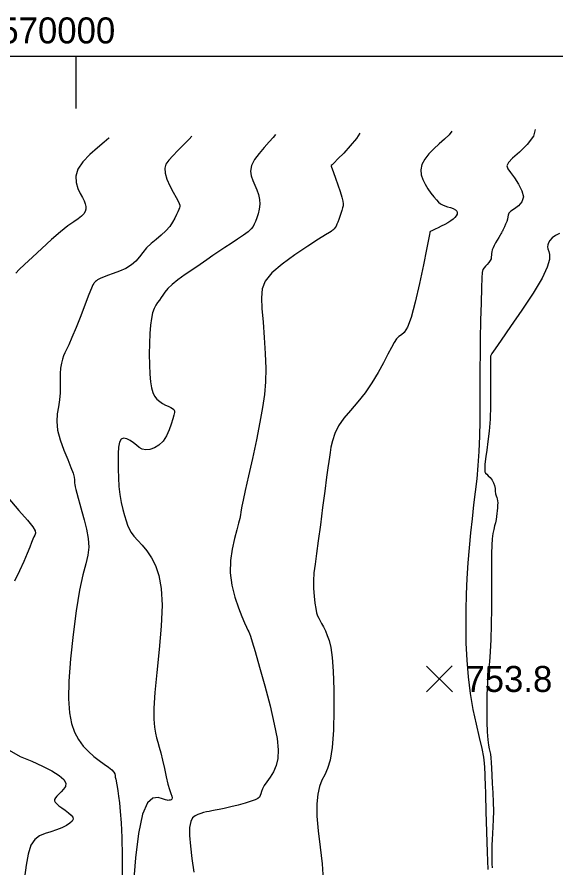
# Model space of a CAD drawing. Extents: x 2566142 to 2571431, y 418755 to 421584.
# Drawn here: x 2569965.9 to 2570277, y 421093.3 to 421584.4 of the extents above; entities that cross this region are included whole.
import ezdxf

# ---------------------------------------------------------------- set-up
doc = ezdxf.new("R2010")
doc.units = 0
for name, color, linetype in [('Contour_ADS_Major', 7, 'Continuous'), ('Contour_ADS_Minor', 7, 'Continuous'), ('Contour_ADS_Spot_Elevation', 7, 'Continuous'), ('Contour_ADS_State_Plane_Border', 7, 'Continuous')]:
    doc.layers.add(name, color=color, linetype=linetype)

# ---------------------------------------------------------------- blocks, each defined once
blk = doc.blocks.new('S750')
at = {"layer": 'Contour_ADS_Spot_Elevation'}
for p, q in [((-0.5, 0.498), (0.5, -0.498)), ((-0.498, -0.5), (0.498, 0.5))]:
    blk.add_line(p, q, dxfattribs=at)

msp = doc.modelspace()

# ---------------------------------------------------------------- linework, layer by layer
at = {"layer": 'Contour_ADS_Major'}
for points in [[(2570163.72, 421517.45), (2570161.83, 421514.35), (2570158.31, 421510.02), (2570154.48, 421505.88), (2570151.16, 421502.51), (2570148.99, 421500.32), (2570147.82, 421499.13), (2570147.34, 421498.61), (2570147.22, 421498.44), (2570147.22, 421498.28), (2570147.37, 421497.81), (2570147.76, 421496.71), (2570148.51, 421494.64), (2570149.67, 421491.45), (2570151.03, 421487.6), (2570152.37, 421483.69), (2570153.43, 421480.35), (2570154.03, 421478.04), (2570154.21, 421476.51), (2570154.09, 421475.37), (2570153.77, 421474.22), (2570153.34, 421472.75), (2570152.84, 421471.04), (2570152.29, 421469.25), (2570151.72, 421467.54), (2570151.16, 421466.04), (2570150.6, 421464.77), (2570150.05, 421463.72), (2570149.53, 421462.87), (2570149.03, 421462.2), (2570148.56, 421461.69), (2570148.13, 421461.29), (2570147.73, 421461), (2570147.27, 421460.69), (2570146.23, 421460.04), (2570143.99, 421458.64), (2570139.93, 421456.09), (2570133.74, 421452.13), (2570126.35, 421447.2), (2570119.02, 421441.85), (2570113, 421436.67), (2570109.22, 421432.02), (2570107.41, 421427.48), (2570106.97, 421422.39), (2570107.32, 421416.12), (2570107.95, 421408.26), (2570108.61, 421399.35), (2570109.16, 421390.15), (2570109.45, 421381.45), (2570109.34, 421373.76), (2570108.77, 421366.55), (2570107.71, 421359.06), (2570106.14, 421350.49), (2570104.07, 421340.41), (2570101.76, 421329.69), (2570099.52, 421319.56), (2570097.68, 421311.22), (2570096.46, 421305.55), (2570095.77, 421302.09), (2570095.39, 421300.04), (2570095.16, 421298.59), (2570094.89, 421297.03), (2570094.47, 421295), (2570093.82, 421292.21), (2570092.83, 421288.4), (2570091.49, 421283.38), (2570090.14, 421277.36), (2570089.18, 421270.65), (2570089.02, 421263.56), (2570089.94, 421256.41), (2570091.64, 421249.57), (2570093.7, 421243.43), (2570095.67, 421238.38), (2570097.22, 421234.69), (2570098.36, 421232.17), (2570099.16, 421230.54), (2570099.72, 421229.48), (2570100.16, 421228.6), (2570100.74, 421227.05), (2570101.73, 421223.88), (2570103.42, 421218.13), (2570105.95, 421209.25), (2570108.97, 421198.33), (2570111.97, 421186.86), (2570114.44, 421176.34), (2570115.99, 421167.93), (2570116.61, 421161.47), (2570116.4, 421156.45), (2570115.45, 421152.38), (2570113.9, 421148.85), (2570112.03, 421145.75), (2570110.14, 421143.08), (2570108.58, 421140.81), (2570107.56, 421138.93), (2570106.97, 421137.39), (2570106.62, 421136.12), (2570106.32, 421135.09), (2570105.85, 421134.22), (2570104.97, 421133.43), (2570103.45, 421132.64), (2570101.02, 421131.75)], [(2570101.02, 421131.75), (2570097.57, 421130.72), (2570093.49, 421129.62), (2570089.3, 421128.57), (2570085.52, 421127.67), (2570082.54, 421127.02), (2570080.25, 421126.56), (2570078.42, 421126.22), (2570076.81, 421125.93), (2570075.21, 421125.62), (2570073.6, 421125.24), (2570071.97, 421124.78), (2570070.34, 421124.2), (2570068.73, 421123.42), (2570067.28, 421122.15), (2570066.16, 421120.03), (2570065.52, 421116.71), (2570065.48, 421111.94), (2570065.96, 421105.88), (2570066.81, 421098.78), (2570067.91, 421090.91)]]:
    msp.add_lwpolyline(points, dxfattribs=at)
at = {"layer": 'Contour_ADS_Minor'}
for points in [[(2570115.17, 421516.52), (2570113.72, 421514.8), (2570111.39, 421512.28), (2570108.56, 421509.17), (2570105.62, 421505.68), (2570103.05, 421502.07), (2570101.29, 421498.61), (2570100.68, 421495.51), (2570101.02, 421492.71), (2570101.95, 421490.06), (2570103.14, 421487.44), (2570104.28, 421484.74), (2570105.22, 421481.97), (2570105.85, 421479.15), (2570106.04, 421476.32), (2570105.74, 421473.53), (2570105.09, 421470.88), (2570104.28, 421468.48), (2570103.51, 421466.44), (2570102.87, 421464.83), (2570102.16, 421463.45), (2570101.07, 421462.09), (2570099.27, 421460.5), (2570096.59, 421458.52), (2570093.23, 421456.23), (2570089.53, 421453.78), (2570085.81, 421451.33), (2570082.33, 421448.99), (2570078.95, 421446.67), (2570075.45, 421444.26), (2570071.62, 421441.65), (2570067.35, 421438.76), (2570062.94, 421435.73), (2570058.82, 421432.75), (2570055.38, 421430.01), (2570052.93, 421427.65), (2570051.27, 421425.65), (2570050.12, 421423.93), (2570049.15, 421422.43), (2570048.13, 421421.05), (2570047.06, 421419.65), (2570046, 421418.05), (2570045.01, 421416.09), (2570044.15, 421413.58), (2570043.44, 421410.43), (2570042.89, 421406.5), (2570042.51, 421401.68), (2570042.3, 421395.96), (2570042.27, 421389.78), (2570042.38, 421383.69), (2570042.63, 421378.24), (2570043, 421373.84), (2570043.54, 421370.41), (2570044.31, 421367.75), (2570045.35, 421365.65), (2570046.7, 421363.93), (2570048.28, 421362.52), (2570049.96, 421361.39), (2570051.64, 421360.47), (2570053.21, 421359.74), (2570054.6, 421359.11), (2570055.72, 421358.53), (2570056.49, 421357.9), (2570056.86, 421357.16), (2570056.85, 421356.12), (2570056.51, 421354.61), (2570055.87, 421352.43), (2570054.96, 421349.49), (2570053.75, 421346.11), (2570052.18, 421342.7), (2570050.21, 421339.65), (2570047.82, 421337.31), (2570045.2, 421335.71), (2570042.59, 421334.83), (2570040.2, 421334.64), (2570038.21, 421335.08), (2570036.49, 421336), (2570034.87, 421337.24), (2570033.16, 421338.64), (2570031.25, 421339.99), (2570029.27, 421341.02), (2570027.44, 421341.39), (2570025.97, 421340.79), (2570025.02, 421338.99), (2570024.5, 421336.13), (2570024.29, 421332.42), (2570024.26, 421328.1), (2570024.3, 421323.38), (2570024.44, 421318.45), (2570024.73, 421313.51), (2570025.24, 421308.73), (2570025.99, 421304.28), (2570026.91, 421300.24), (2570027.9, 421296.66), (2570028.86, 421293.61), (2570029.73, 421291.1), (2570030.66, 421288.95), (2570031.82, 421286.92), (2570033.41, 421284.79), (2570035.55, 421282.36), (2570038.07, 421279.53)], [(2570216.92, 421518.47), (2570215.29, 421516.43), (2570212.69, 421513.96), (2570209.68, 421511.27), (2570206.58, 421508.37), (2570203.7, 421505.34), (2570201.31, 421502.26), (2570199.69, 421499.2), (2570199.05, 421496.23), (2570199.25, 421493.35), (2570200.12, 421490.56), (2570201.45, 421487.86), (2570203.05, 421485.24), (2570204.78, 421482.8), (2570206.48, 421480.64), (2570208.01, 421478.87), (2570209.27, 421477.56), (2570210.39, 421476.62), (2570211.51, 421475.95), (2570212.82, 421475.41), (2570214.4, 421474.91), (2570216.11, 421474.4), (2570217.71, 421473.84), (2570218.99, 421473.19), (2570219.77, 421472.44), (2570220.07, 421471.59), (2570219.94, 421470.67), (2570219.47, 421469.7), (2570218.69, 421468.71), (2570217.63, 421467.7), (2570216.29, 421466.68), (2570214.66, 421465.65), (2570212.8, 421464.62), (2570210.84, 421463.63), (2570208.97, 421462.74), (2570207.38, 421462), (2570206.19, 421461.44), (2570205.38, 421461.05), (2570204.86, 421460.78), (2570204.55, 421460.6), (2570204.36, 421460.47), (2570204.26, 421460.38), (2570204.23, 421460.31), (2570204.23, 421460.24), (2570204.2, 421460.02), (2570204, 421458.88), (2570203.43, 421455.91), (2570202.3, 421450.2), (2570200.5, 421441.29), (2570198.23, 421430.57), (2570195.76, 421419.87), (2570193.36, 421411.03), (2570191.23, 421405.39), (2570189.39, 421402.38), (2570187.78, 421400.94), (2570186.35, 421400), (2570185.02, 421398.65), (2570183.64, 421396.6), (2570182.02, 421393.69), (2570179.99, 421389.79), (2570177.41, 421384.85), (2570174.31, 421379.2), (2570170.76, 421373.27), (2570166.82, 421367.5), (2570162.62, 421362.22), (2570158.44, 421357.37), (2570154.63, 421352.81), (2570151.51, 421348.4), (2570149.34, 421344.04), (2570147.97, 421339.87), (2570147.15, 421336.12), (2570146.65, 421332.97), (2570146.26, 421330.46), (2570145.85, 421327.86), (2570145.32, 421324.27), (2570144.58, 421318.78), (2570143.56, 421310.84), (2570142.35, 421301.3), (2570141.07, 421291.34), (2570139.84, 421282.17), (2570138.78, 421274.69), (2570137.93, 421268.69), (2570137.34, 421263.64), (2570137.05, 421259.03), (2570137.08, 421254.48), (2570137.37, 421250.11), (2570137.82, 421246.18), (2570138.34, 421242.94), (2570138.87, 421240.55), (2570139.43, 421238.81), (2570140.07, 421237.39), (2570140.83, 421235.99), (2570141.76, 421234.35), (2570142.81, 421232.4), (2570143.92, 421230.13), (2570145.04, 421227.54), (2570146.09, 421224.49), (2570147.05, 421220.45), (2570147.85, 421214.78), (2570148.46, 421206.84), (2570148.82, 421196.33)], [(2570265.06, 421519.39), (2570264.04, 421515.66), (2570260.47, 421510.83), (2570256.01, 421506.42), (2570252.01, 421502.84), (2570249.58, 421500.36), (2570248.73, 421498.56), (2570249.2, 421496.86), (2570250.74, 421494.67), (2570253.03, 421491.58), (2570255.47, 421487.89), (2570257.42, 421484.06), (2570258.2, 421480.53), (2570257.38, 421477.69), (2570255.45, 421475.47), (2570253.11, 421473.75), (2570251.07, 421472.38), (2570249.87, 421471.21), (2570249.35, 421470.13), (2570249.17, 421469.03), (2570249, 421467.8), (2570248.59, 421466.35), (2570247.99, 421464.83), (2570247.33, 421463.39), (2570246.75, 421462.2), (2570246.35, 421461.39), (2570246.11, 421460.89), (2570245.97, 421460.6), (2570245.87, 421460.4), (2570245.75, 421460.19), (2570245.57, 421459.87), (2570245.25, 421459.31), (2570244.74, 421458.43), (2570244, 421457.16), (2570243.12, 421455.63), (2570242.21, 421454), (2570241.38, 421452.45), (2570240.73, 421451.11), (2570240.25, 421449.95), (2570239.95, 421448.92), (2570239.79, 421447.93), (2570239.74, 421446.94), (2570239.7, 421445.93), (2570239.53, 421444.89), (2570239.11, 421443.82), (2570238.35, 421442.71), (2570237.38, 421441.61), (2570236.37, 421440.57), (2570235.49, 421439.62), (2570234.87, 421438.68), (2570234.46, 421437.02), (2570234.2, 421433.78), (2570233.99, 421428.11), (2570233.77, 421419.53), (2570233.54, 421409.17), (2570233.34, 421398.56), (2570233.2, 421389.22), (2570233.12, 421382.23), (2570233.1, 421376.88), (2570233.12, 421372.02), (2570233.14, 421366.49), (2570233.14, 421359.43), (2570233.08, 421351.19), (2570232.89, 421342.4), (2570232.54, 421333.7), (2570231.99, 421325.57), (2570231.26, 421317.9), (2570230.42, 421310.4), (2570229.51, 421302.8), (2570228.58, 421294.87), (2570227.68, 421286.61), (2570226.86, 421278.08), (2570226.14, 421269.33), (2570225.58, 421260.41), (2570225.18, 421251.32), (2570224.96, 421242.06), (2570224.93, 421232.6), (2570225.09, 421222.96), (2570225.52, 421213.24), (2570226.3, 421203.56), (2570227.48, 421194.04), (2570229.1, 421184.83), (2570230.94, 421176.23), (2570232.73, 421168.56), (2570234.19, 421162.17), (2570235.13, 421157.27), (2570235.63, 421153.72), (2570235.83, 421151.27), (2570235.87, 421149.68), (2570235.9, 421148.72), (2570235.92, 421148.21), (2570235.93, 421147.99), (2570235.95, 421147.91), (2570235.95, 421147.85), (2570235.96, 421147.76), (2570235.96, 421147.64), (2570235.97, 421147.5), (2570235.98, 421147.34), (2570235.99, 421147.16), (2570236, 421146.98), (2570236, 421146.8)], [(2570019.19, 421514.69), (2570018.92, 421514.45), (2570016.17, 421512.15), (2570012.32, 421508.96), (2570007.98, 421505.08), (2570003.96, 421500.85), (2570001.05, 421496.58), (2569999.84, 421492.54), (2570000.01, 421488.83), (2570001.04, 421485.51), (2570002.4, 421482.63), (2570003.62, 421480.23), (2570004.6, 421478.23), (2570005.29, 421476.51), (2570005.66, 421474.97), (2570005.67, 421473.52), (2570005.27, 421472.12), (2570004.42, 421470.75), (2570003.08, 421469.39), (2570001.19, 421467.96), (2569998.63, 421466.2), (2569995.28, 421463.79), (2569990.99, 421460.41), (2569985.77, 421455.91), (2569980.14, 421450.82), (2569974.77, 421445.81), (2569970.29, 421441.59), (2569967.18, 421438.64), (2569965.12, 421436.63)], [(2570066.77, 421515.6), (2570065.2, 421513.96), (2570062.04, 421510.7), (2570058.79, 421507.33), (2570055.82, 421504.25), (2570053.47, 421501.71), (2570051.88, 421499.46), (2570051.14, 421497.13), (2570051.33, 421494.34), (2570052.45, 421490.87), (2570054.17, 421487.05), (2570056.07, 421483.35), (2570057.77, 421480.24), (2570058.92, 421478.07), (2570059.56, 421476.68), (2570059.81, 421475.76), (2570059.8, 421475.03), (2570059.61, 421474.22), (2570059.26, 421473.22), (2570058.73, 421471.95), (2570057.99, 421470.34), (2570057.01, 421468.34), (2570055.72, 421466.03), (2570054.03, 421463.55), (2570051.86, 421461.02), (2570049.18, 421458.53), (2570046.21, 421456.08), (2570043.26, 421453.61), (2570040.62, 421451.11), (2570038.47, 421448.53), (2570036.56, 421445.98), (2570034.52, 421443.53), (2570031.98, 421441.29), (2570028.72, 421439.34), (2570025.03, 421437.68), (2570021.38, 421436.3), (2570018.22, 421435.19), (2570015.87, 421434.32), (2570014.24, 421433.64), (2570013.15, 421433.1), (2570012.37, 421432.63), (2570011.75, 421432.19), (2570011.23, 421431.78), (2570010.81, 421431.4), (2570010.48, 421431.07), (2570010.17, 421430.69), (2570009.72, 421429.8), (2570008.88, 421427.84), (2570007.44, 421424.23), (2570005.28, 421418.69), (2570002.67, 421412), (2569999.97, 421405.2), (2569997.58, 421399.36), (2569995.76, 421395.25), (2569994.46, 421392.54), (2569993.51, 421390.64), (2569992.76, 421388.93), (2569992.1, 421386.94), (2569991.52, 421384.55), (2569991.09, 421381.77), (2569990.84, 421378.62), (2569990.79, 421375.13), (2569990.82, 421371.36), (2569990.76, 421367.45), (2569990.45, 421363.47), (2569989.82, 421359.5), (2569989.17, 421355.38), (2569988.88, 421350.91), (2569989.34, 421345.91), (2569990.79, 421340.29), (2569992.88, 421334.47), (2569995.14, 421329), (2569997.06, 421324.4), (2569998.29, 421321.07), (2569998.91, 421318.84), (2569999.14, 421317.37), (2569999.16, 421316.34), (2569999.17, 421315.46), (2569999.24, 421314.51), (2569999.43, 421313.32), (2569999.79, 421311.72), (2570000.36, 421309.54), (2570001.16, 421306.72), (2570002.16, 421303.23), (2570003.38, 421299.02), (2570004.75, 421294.13), (2570006.04, 421288.84), (2570006.98, 421283.49), (2570007.29, 421278.44), (2570006.77, 421273.8), (2570005.57, 421268.79), (2570003.9, 421262.38), (2570001.98, 421253.54), (2570000.03, 421241.68), (2569998.24, 421227.94), (2569996.8, 421213.9), (2569995.9, 421201.13), (2569995.69, 421190.85), (2569996.17, 421182.87), (2569997.31, 421176.64), (2569999.05, 421171.62)], [(2570279.05, 421459.52), (2570276.7, 421458.39), (2570274.87, 421457), (2570273.55, 421455.51), (2570272.69, 421454.1), (2570272.26, 421452.89), (2570272.2, 421451.76), (2570272.42, 421450.57), (2570272.85, 421449.14), (2570273.31, 421447.25), (2570273.27, 421444.4), (2570272.05, 421440.07), (2570269.03, 421433.68), (2570263.85, 421425.04), (2570257.4, 421415.24), (2570250.84, 421405.73), (2570245.37, 421397.94), (2570241.86, 421392.93), (2570240.05, 421390.27), (2570239.36, 421389.13), (2570239.24, 421388.69), (2570239.2, 421388.19), (2570239.18, 421387.05), (2570239.17, 421384.78), (2570239.2, 421380.87), (2570239.27, 421375.02), (2570239.31, 421367.78), (2570239.23, 421359.93), (2570238.96, 421352.23), (2570238.43, 421345.33), (2570237.76, 421339.4), (2570237.07, 421334.5), (2570236.49, 421330.67), (2570236.13, 421327.92), (2570235.95, 421326.05), (2570235.89, 421324.83), (2570235.89, 421324.01), (2570235.9, 421323.4), (2570235.91, 421322.91), (2570235.91, 421322.53), (2570235.93, 421322.23), (2570235.97, 421321.96), (2570236.11, 421321.65), (2570236.43, 421321.22), (2570237.04, 421320.59), (2570237.96, 421319.69), (2570239.06, 421318.54), (2570240.15, 421317.19), (2570241.04, 421315.65), (2570241.58, 421314), (2570241.87, 421312.31), (2570242.03, 421310.71), (2570242.2, 421309.3), (2570242.47, 421308.15), (2570242.81, 421307.17), (2570243.13, 421306.24), (2570243.35, 421305.22), (2570243.42, 421304.01), (2570243.37, 421302.63), (2570243.24, 421301.1), (2570243.07, 421299.48)], [(2569960.53, 421307.07), (2569966.86, 421299.67), (2569971.94, 421294.01), (2569974.99, 421290.21), (2569976.32, 421287.85), (2569976.52, 421286.43), (2569976.14, 421285.43), (2569975.66, 421284.37), (2569975.09, 421282.99), (2569974.31, 421281.06), (2569973.22, 421278.37), (2569971.73, 421274.75), (2569969.79, 421270.22), (2569967.39, 421264.86), (2569964.48, 421258.77)], [(2570243.07, 421299.48), (2570242.91, 421297.79), (2570242.72, 421296.06), (2570242.47, 421294.3), (2570242.11, 421292.53), (2570241.63, 421290.73), (2570241.09, 421288.72), (2570240.57, 421286.32), (2570240.18, 421283.32), (2570239.95, 421279.52), (2570239.87, 421274.73), (2570239.87, 421268.76), (2570239.89, 421261.41), (2570239.88, 421252.66), (2570239.81, 421243.15), (2570239.66, 421233.69), (2570239.4, 421225.1), (2570239.04, 421218.01), (2570238.61, 421212.28), (2570238.17, 421207.62), (2570237.78, 421203.72), (2570237.49, 421200.26), (2570237.29, 421196.87), (2570237.17, 421193.14), (2570237.11, 421188.69), (2570237.11, 421183.3), (2570237.18, 421177.49), (2570237.34, 421171.93), (2570237.61, 421167.32), (2570238, 421164.13), (2570238.45, 421162.03), (2570238.88, 421160.47), (2570239.24, 421158.9), (2570239.47, 421156.85), (2570239.62, 421154.19), (2570239.75, 421150.85), (2570239.93, 421146.77), (2570240.21, 421141.97), (2570240.51, 421136.69), (2570240.77, 421131.29), (2570240.89, 421126.07), (2570240.81, 421121.32), (2570240.6, 421117.03), (2570240.34, 421113.15), (2570240.13, 421109.62), (2570240.02, 421106.39), (2570239.99, 421103.42), (2570240.02, 421100.68), (2570240.07, 421098.12), (2570240.1, 421095.7), (2570240.15, 421093.27)], [(2570038.07, 421279.53), (2570040.78, 421276.22), (2570043.44, 421272.36), (2570045.87, 421267.8), (2570047.83, 421262.07), (2570049.15, 421254.64), (2570049.6, 421244.98), (2570049.09, 421232.86), (2570047.95, 421219.44), (2570046.61, 421206.16), (2570045.51, 421194.49), (2570044.97, 421185.55), (2570044.94, 421179.08), (2570045.29, 421174.46), (2570045.84, 421171.07), (2570046.49, 421168.34), (2570047.21, 421165.82), (2570048.02, 421163.08), (2570048.92, 421159.71), (2570049.9, 421155.44), (2570050.95, 421150.67), (2570052.01, 421145.92), (2570053.03, 421141.74), (2570053.98, 421138.55), (2570054.76, 421136.27), (2570055.3, 421134.72), (2570055.5, 421133.7), (2570055.34, 421133.05), (2570054.89, 421132.66), (2570054.31, 421132.45), (2570053.74, 421132.34), (2570053.24, 421132.27), (2570052.61, 421132.32), (2570051.59, 421132.58), (2570049.92, 421133.15), (2570047.42, 421133.86), (2570044.39, 421133.56), (2570041.23, 421130.84), (2570038.35, 421124.29), (2570036.06, 421113.13), (2570034.37, 421099.14), (2570033.21, 421084.72)], [(2570148.82, 421196.33), (2570148.87, 421184.45), (2570148.57, 421172.73), (2570147.84, 421162.72), (2570146.67, 421155.55), (2570145.19, 421150.68), (2570143.56, 421147.13), (2570141.96, 421143.97), (2570140.56, 421140.34), (2570139.49, 421135.85), (2570138.93, 421130.25), (2570139, 421123.27), (2570139.78, 421114.79), (2570140.92, 421105.35), (2570141.98, 421095.64), (2570142.55, 421086.35)], [(2569999.05, 421171.62), (2570001.34, 421167.34), (2570004.06, 421163.64), (2570007.07, 421160.45), (2570010.21, 421157.68), (2570013.35, 421155.26), (2570016.27, 421153.17), (2570018.79, 421151.37), (2570020.69, 421149.85), (2570021.85, 421148.59), (2570022.41, 421147.56), (2570022.58, 421146.74), (2570022.6, 421146.12), (2570022.64, 421145.64), (2570022.73, 421145.17), (2570022.89, 421144.55), (2570023.1, 421143.6), (2570023.37, 421142.19), (2570023.69, 421140.26), (2570024.08, 421137.75), (2570024.53, 421134.63), (2570025.03, 421130.78), (2570025.53, 421125.84), (2570026, 421119.36), (2570026.36, 421110.89), (2570026.59, 421100.19), (2570026.69, 421087.81)], [(2569961.29, 421161.19), (2569967.77, 421157.69), (2569974.41, 421154.86), (2569980.6, 421152.1), (2569985.99, 421149.36), (2569990.23, 421146.74), (2569992.99, 421144.33), (2569994.09, 421142.2), (2569993.87, 421140.34)], [(2570236, 421146.8), (2570236, 421146.48), (2570236.03, 421145.17), (2570236.12, 421141.89), (2570236.31, 421135.63), (2570236.6, 421125.89), (2570236.96, 421114.14), (2570237.32, 421102.36), (2570237.62, 421092.49)], [(2569993.87, 421140.34), (2569992.81, 421138.71), (2569991.4, 421137.27), (2569990.06, 421135.97), (2569988.93, 421134.81), (2569988.08, 421133.78), (2569987.6, 421132.85), (2569987.55, 421132.01), (2569987.95, 421131.19), (2569988.8, 421130.29), (2569990.11, 421129.24), (2569991.85, 421127.98), (2569993.78, 421126.58), (2569995.63, 421125.15), (2569997.12, 421123.77), (2569998.03, 421122.53), (2569998.25, 421121.38), (2569997.75, 421120.25), (2569996.47, 421119.07), (2569994.4, 421117.8), (2569991.72, 421116.5), (2569988.64, 421115.25), (2569985.35, 421114.13), (2569982.07, 421113.14), (2569978.97, 421111.86), (2569976.2, 421109.77), (2569973.94, 421106.38), (2569972.29, 421101.33), (2569971.1, 421094.95), (2569970.14, 421087.75)]]:
    msp.add_lwpolyline(points, dxfattribs=at)
at = {"layer": 'Contour_ADS_State_Plane_Border'}
msp.add_line((2570000, 421531.67), (2570000, 421561.67), dxfattribs=at)
msp.add_lwpolyline([(2566164.43, 418777.5), (2571407.81, 418777.5), (2571407.81, 421561.67), (2566164.43, 421561.67), (2566164.43, 418777.5)], close=True, dxfattribs=at)

# ---------------------------------------------------------------- block references
at = {"layer": 'Contour_ADS_Spot_Elevation', "xscale": 15, "yscale": 15}
msp.add_blockref('S750', (2570209.73, 421202.37), dxfattribs=at)

# ---------------------------------------------------------------- texts
at = {"layer": 'Contour_ADS_Spot_Elevation'}
msp.add_text('753.8', height=15, dxfattribs=at).set_placement((2570224.73, 421194.87))
at = {"layer": 'Contour_ADS_State_Plane_Border'}
msp.add_text(' E 2570000', height=15, dxfattribs=at).set_placement((2569920, 421569.17))

doc.saveas('drawing.dxf')
